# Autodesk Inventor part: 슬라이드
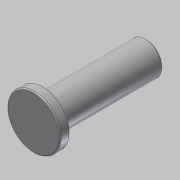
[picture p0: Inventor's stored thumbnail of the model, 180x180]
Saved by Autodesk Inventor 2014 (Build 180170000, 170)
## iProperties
Company: 한국ATC센터
Created: 2015-11
Part Number: 슬라이드
Document SubType Name: Modeling
Designer: mdu
Density: 7.86 g/cm^3
Material: 강철, 연강
Mass: 53.0481 g
Surface Area: 25.6984 cm^2
Volume: 6.74912 cm^3
Appearance: 강철
Author: mdu
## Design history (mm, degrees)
sketch "스케치1"
  geometry: L1 (13.5, 41)-(13.5, 74) reference; L2 (13.5, 74)-(26.5, 74) reference; L3 (20, 74)-(20, 29); L4 (20, 74)-(13.5, 74); L5 (13.5, 74)-(13.5, 33); L6 (13.5, 33)-(9.5, 33); L7 (9.5, 33)-(9.5, 29); L8 (20, 73.5)-(13.5, 73.5); L9 (20, 29)-(9.5, 29); 1 further point
  constraints: 16 end point, 4 perpendicular, 3 point on line, 1 collinear, 1 midpoint, 1 parallel, 1 vertical, 2 other
  dimensions: "d0" = 45 distance of L3.start L3.end; "d1" = 21 diameter of L7 L3; "d2" = 4 distance from line of L3.end L6; "d4" = 0.5 distance between parallel lines of L8 L2
revolve "회전1" sketch "스케치1" stored, may be unused: angle "d5" = 90 deg
fillet "모깎기1" dims "d6" = 0.5
chamfer "모따기1" distance "d9" = 0.5; stored, may be unused: second distance "d10" = 2, angle "d11" = 45 deg
node "솔리드1"
node "참조1"
